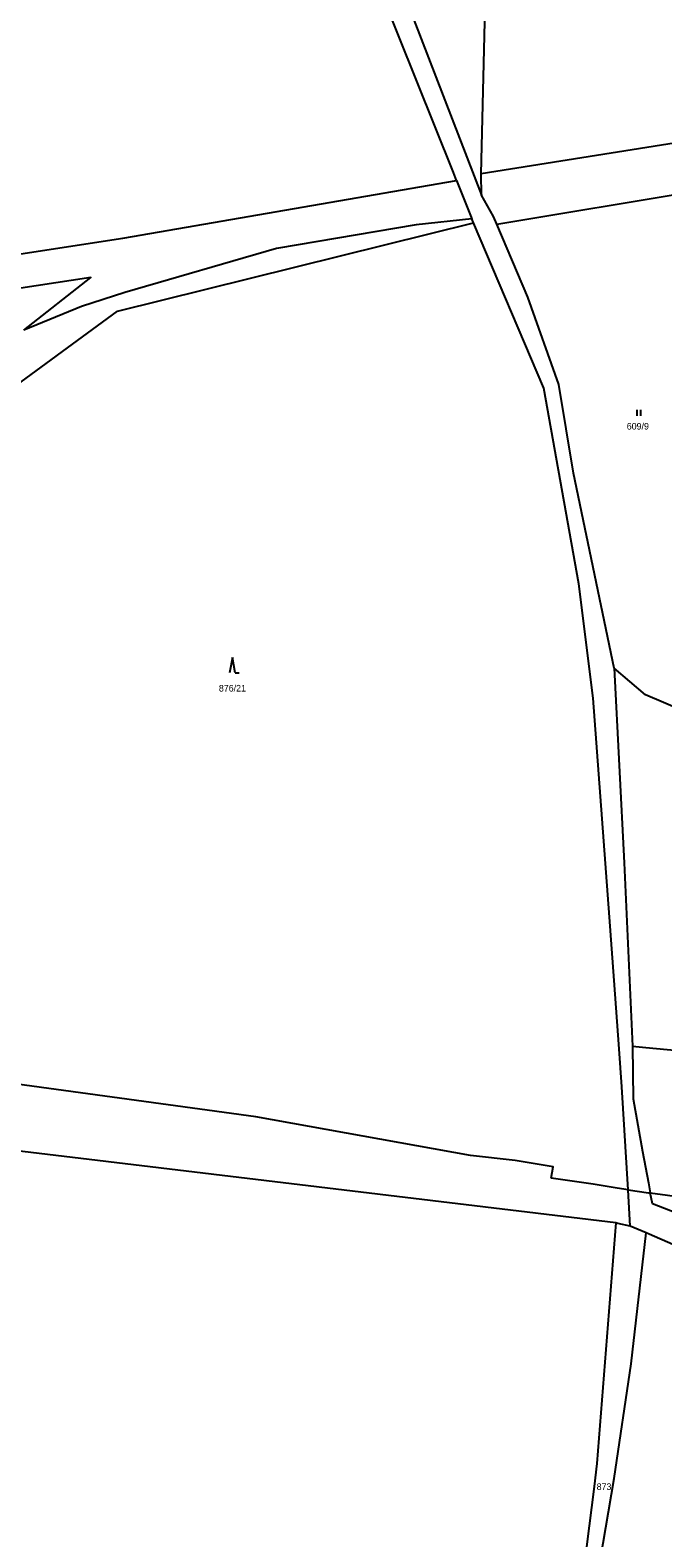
# Model space of a CAD drawing. Extents: x -7483133 to -743169, y -11317770 to -1127091.
# Drawn here: x -747334.5 to -747171.9, y -1133122.3 to -1132734.9 of the extents above; entities that cross this region are included whole.
import ezdxf

# ---------------------------------------------------------------- set-up
doc = ezdxf.new("R2010")
doc.units = 0
for name, color, linetype in [('Hranice parcel', 7, 'Continuous'), ('Parcelní čísla', 7, 'Continuous'), ('Značky kultur', 7, 'Continuous')]:
    doc.layers.add(name, color=color, linetype=linetype)

msp = doc.modelspace()

# ---------------------------------------------------------------- linework, layer by layer
at = {"layer": 'Hranice parcel'}
for p, q in [((-747155.28, -1132761.69), (-747218.59, -1132771.84)), ((-747310.66, -1132788.33), (-747224.93, -1132773.5)), ((-747224.93, -1132773.5), (-747220.98, -1132783.4)), ((-747218.53, -1132777.27), (-747218.59, -1132771.84)), ((-747218.53, -1132777.27), (-747218.59, -1132771.84)), ((-747214.61, -1132784.76), (-747155.49, -1132774.88)), ((-747312.07, -1132807.15), (-747220.56, -1132784.45)), ((-747220.56, -1132784.45), (-747220.98, -1132783.4)), ((-747388.83, -1132863.32), (-747312.07, -1132807.15)), ((-747180.38, -1133042.21), (-747180.82, -1133032.94)), ((-747175.17, -1133033.7), (-747125.15, -1133040.39)), ((-747176.22, -1133043.98), (-747180.38, -1133042.21))]:
    msp.add_line(p, q, dxfattribs=at)
for points in [[(-747224.93, -1132773.5), (-747225.72, -1132771.51), (-747263.19, -1132677.97), (-747301.9, -1132583.56), (-747308.87, -1132506.03), (-747317.24, -1132458.97), (-747337.26, -1132332.85), (-747334.04, -1132323.78), (-747320.31, -1132313.98), (-747296.72, -1132306.18), (-747289.13, -1132303.67), (-747262.97, -1132295.03), (-747251.22, -1132292.4), (-747244.35, -1132283.92), (-747248.16, -1132266.52)], [(-747295.89, -1132582.7), (-747279.64, -1132623.02), (-747268.86, -1132651.49), (-747237.8, -1132727.36), (-747218.53, -1132777.27)], [(-747218.59, -1132771.84), (-747217.53, -1132725.58), (-747209.76, -1132658.63), (-747207.17, -1132631.63), (-747205.5, -1132602.3)], [(-747218.59, -1132771.84), (-747217.53, -1132725.58), (-747209.76, -1132658.63), (-747207.17, -1132631.63), (-747205.5, -1132602.3)], [(-747214.61, -1132784.76), (-747215.45, -1132782.81), (-747218.53, -1132777.27)], [(-747214.61, -1132784.76), (-747215.45, -1132782.81), (-747218.53, -1132777.27)], [(-747220.98, -1132783.4), (-747235.31, -1132784.92), (-747271.23, -1132790.99), (-747310.12, -1132802.34), (-747321.3, -1132805.93), (-747336.09, -1132812)], [(-747180.82, -1133032.94), (-747182.45, -1133006.42), (-747183.17, -1132996.67), (-747184.46, -1132979.1), (-747185.65, -1132962.8), (-747189.83, -1132906.57), (-747193.53, -1132877.19), (-747202.48, -1132826.92), (-747220.56, -1132784.45)], [(-747184.42, -1132898.81), (-747194.87, -1132848.77), (-747198.69, -1132825.98), (-747206.6, -1132803.47), (-747214.61, -1132784.76)], [(-747184.42, -1132898.81), (-747194.87, -1132848.77), (-747198.69, -1132825.98), (-747206.6, -1132803.47), (-747214.61, -1132784.76)], [(-747748.04, -1132937.99), (-747684.48, -1132912.3), (-747622.32, -1132886.34), (-747568.51, -1132864.74), (-747523.85, -1132846.3), (-747479.14, -1132827.98), (-747446.19, -1132813.87), (-747416.59, -1132806.04), (-747376.53, -1132798.49), (-747310.66, -1132788.33)], [(-747336.09, -1132812), (-747318.86, -1132798.49), (-747370.14, -1132806.27)], [(-747161.9, -1132911.88), (-747176.42, -1132905.74), (-747184.42, -1132898.81)], [(-747184.42, -1132898.81), (-747181.92, -1132948.88), (-747179.76, -1132996)], [(-747161.9, -1132911.88), (-747176.42, -1132905.74), (-747184.42, -1132898.81)], [(-747200.64, -1133029.94), (-747200.15, -1133026.98), (-747209.89, -1133025.38), (-747221.38, -1133024.08), (-747276.48, -1133014.17), (-747452.96, -1132989.98)], [(-747179.76, -1132996), (-747176.3, -1132996.32), (-747118.84, -1133001.68), (-747120.7, -1133013.08)], [(-747179.76, -1132996), (-747179.59, -1133009.51), (-747177.2, -1133023.01), (-747175.67, -1133031.09), (-747175.17, -1133033.7)], [(-747183.98, -1133041.41), (-747321.44, -1133024.87), (-747460.68, -1133008.17)], [(-747180.82, -1133032.94), (-747183.64, -1133032.48), (-747189.84, -1133031.47), (-747200.64, -1133029.94)], [(-747180.82, -1133032.94), (-747175.62, -1133033.64), (-747175.17, -1133033.7)], [(-747130.75, -1133053.53), (-747174.63, -1133036.48), (-747175.17, -1133033.7)], [(-747183.98, -1133041.41), (-747188.86, -1133103.23), (-747189.61, -1133109.13), (-747192.87, -1133134.77), (-747198.76, -1133141.14), (-747218.29, -1133162.23), (-747260.55, -1133181.81), (-747256.49, -1133186.83), (-747216.5, -1133165.46), (-747200.93, -1133148.71), (-747189.41, -1133136.32), (-747184.44, -1133107.11), (-747180.1, -1133077.6), (-747176.22, -1133043.98)], [(-747180.38, -1133042.21), (-747183.52, -1133041.51), (-747183.98, -1133041.41)], [(-747152.49, -1133054.34), (-747175.49, -1133044.3), (-747176.22, -1133043.98)]]:
    msp.add_lwpolyline(points, dxfattribs=at)
at = {"layer": 'Značky kultur'}
for p, q in [((-747178.57, -1132833.98), (-747178.57, -1132832.48)), ((-747177.57, -1132833.98), (-747177.57, -1132832.48)), ((-747282.53, -1132896.08), (-747283.28, -1132900.08)), ((-747281.78, -1132900.08), (-747282.53, -1132896.08)), ((-747281.78, -1132900.08), (-747280.78, -1132900.08))]:
    msp.add_line(p, q, dxfattribs=at)

# ---------------------------------------------------------------- texts
at = {"layer": 'Parcelní čísla'}
for s, p in [('609/9', (-747181.21, -1132837.53)), ('876/21', (-747286, -1132904.85)), ('873', (-747188.95, -1133110.04))]:
    msp.add_text(s, height=1.7, dxfattribs=at).set_placement(p)

doc.saveas('drawing.dxf')
